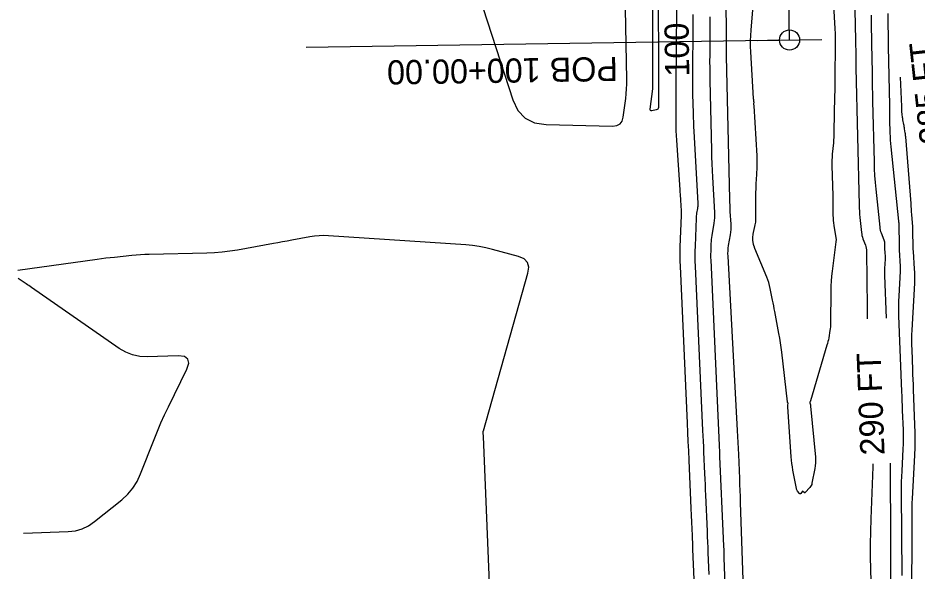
# Model space of a CAD drawing. Extents: x 1768942 to 1774819, y 723037 to 732099.
# Drawn here: x 1770638.6 to 1770861.8, y 724105.6 to 724242.8 of the extents above; entities that cross this region are included whole.
import ezdxf

# ---------------------------------------------------------------- set-up
doc = ezdxf.new("R2010")
doc.units = 0
for name, color, linetype in [('R_Contour Annot', 7, 'Continuous'), ('R_Contours', 7, 'Continuous'), ('R_Horz Alg', 7, 'Continuous'), ('R_Horz Alg Annot', 7, 'Continuous')]:
    doc.layers.add(name, color=color, linetype=linetype)

msp = doc.modelspace()

# ---------------------------------------------------------------- linework, layer by layer
at = {"layer": 'R_Contours'}
for points in [[(1770818.67, 724101), (1770817.99, 724122.58), (1770817.94, 724124.06), (1770817.88, 724125.55), (1770817.83, 724127.04), (1770817.77, 724128.52), (1770817.51, 724134.47), (1770817.45, 724135.96), (1770817.38, 724137.45), (1770817.3, 724138.93), (1770817.22, 724140.42), (1770814.87, 724183.68), (1770814.85, 724184.34), (1770814.87, 724185.01), (1770814.93, 724185.67), (1770815.02, 724186.33), (1770815.46, 724188.97), (1770815.55, 724189.63), (1770815.61, 724190.29), (1770815.63, 724190.95), (1770815.61, 724191.62), (1770815.43, 724194.81), (1770815.4, 724195.57), (1770815.36, 724196.32), (1770815.34, 724197.08), (1770815.32, 724197.83), (1770814.51, 724233.31), (1770814.5, 724233.99), (1770814.49, 724234.67), (1770814.49, 724235.35), (1770814.49, 724236.03), (1770814.51, 724238.78), (1770814.51, 724239.45), (1770814.51, 724240.11), (1770814.5, 724240.78), (1770814.48, 724241.44), (1770813.28, 724283.02)], [(1770845.74, 724278.99), (1770846.44, 724240.38), (1770846.46, 724239.55), (1770846.47, 724238.71), (1770846.49, 724237.88), (1770846.5, 724237.05), (1770846.56, 724233.71), (1770846.58, 724232.88), (1770846.59, 724232.05), (1770846.61, 724231.21), (1770846.63, 724230.38), (1770847.4, 724196.35), (1770847.43, 724195.59), (1770847.47, 724194.83), (1770847.53, 724194.07), (1770847.6, 724193.31), (1770847.99, 724189.59), (1770848.04, 724189.18), (1770848.12, 724188.78), (1770848.23, 724188.38), (1770848.37, 724187.99), (1770848.96, 724186.44), (1770849.09, 724186.05), (1770849.18, 724185.66), (1770849.24, 724185.25), (1770849.26, 724184.84), (1770849.39, 724170.97), (1770849.43, 724168.51), (1770849.44, 724168.17)], [(1770750.93, 724254.89), (1770761.48, 724222.47), (1770762.72, 724219.84), (1770764.51, 724217.95), (1770766.84, 724216.78), (1770769.71, 724216.34), (1770786.23, 724215.94), (1770787.27, 724216.06), (1770788.06, 724216.48), (1770788.59, 724217.19), (1770788.87, 724218.2), (1770789.48, 724222.83), (1770789.61, 724223.99), (1770789.7, 724225.16), (1770789.75, 724226.32), (1770789.75, 724227.49), (1770789.45, 724245.06)], [(1770797.55, 724250.14), (1770797.6, 724228.6), (1770797.6, 724228.31), (1770797.6, 724228.02), (1770797.6, 724227.72), (1770797.59, 724227.43), (1770797.58, 724226.25), (1770797.58, 724225.95), (1770797.58, 724225.66), (1770797.58, 724225.37), (1770797.58, 724225.07), (1770797.58, 724220.6), (1770797.55, 724220.35), (1770797.45, 724220.16), (1770797.28, 724220.03), (1770797.05, 724219.95), (1770795.98, 724219.75), (1770795.75, 724219.74), (1770795.6, 724219.81), (1770795.52, 724219.95), (1770795.52, 724220.18), (1770796.18, 724225.21), (1770796.21, 724225.5), (1770796.23, 724225.78), (1770796.24, 724226.07), (1770796.24, 724226.36), (1770796.22, 724227.51), (1770796.22, 724227.8), (1770796.22, 724228.09), (1770796.21, 724228.38), (1770796.21, 724228.67), (1770796.18, 724250.31)], [(1770841.07, 724245.85), (1770841.39, 724240.15), (1770841.45, 724238.87), (1770841.49, 724237.59), (1770841.5, 724236.31), (1770841.5, 724235.03), (1770841.42, 724229.08), (1770841.39, 724227.66), (1770841.37, 724226.24), (1770841.35, 724224.82), (1770841.33, 724223.4), (1770841.17, 724214.59), (1770841.15, 724213.88), (1770841.12, 724213.17), (1770841.07, 724212.47), (1770841.01, 724211.77), (1770840.74, 724208.95), (1770840.69, 724208.25), (1770840.65, 724207.54), (1770840.64, 724206.84), (1770840.65, 724206.13), (1770840.85, 724198.72), (1770840.87, 724198.1), (1770840.88, 724197.49), (1770840.89, 724196.87), (1770840.89, 724196.25), (1770840.91, 724193.77), (1770840.93, 724193.16), (1770840.97, 724192.55), (1770841.04, 724191.94), (1770841.13, 724191.33), (1770841.72, 724187.72), (1770841.73, 724187.71), (1770841.73, 724187.7), (1770841.72, 724187.69), (1770841.72, 724187.67), (1770841.71, 724187.63), (1770841.71, 724187.62), (1770841.7, 724187.61), (1770841.7, 724187.6), (1770841.7, 724187.59), (1770841.65, 724187.38), (1770841.64, 724187.34), (1770841.64, 724187.3), (1770841.63, 724187.25), (1770841.62, 724187.21), (1770840.71, 724179.97), (1770840.57, 724178.75), (1770840.47, 724177.52), (1770840.41, 724176.3), (1770840.38, 724175.07), (1770840.32, 724167.09), (1770840.31, 724166.62), (1770840.28, 724166.16), (1770840.23, 724165.7), (1770840.16, 724165.25), (1770839.85, 724163.42), (1770839.77, 724162.97), (1770839.67, 724162.51), (1770839.56, 724162.06), (1770839.43, 724161.62), (1770835.38, 724147.83), (1770835.36, 724147.79), (1770835.34, 724147.74), (1770835.32, 724147.7), (1770835.29, 724147.65), (1770835.19, 724147.48), (1770835.17, 724147.44), (1770835.16, 724147.39), (1770835.16, 724147.34), (1770835.17, 724147.3), (1770835.3, 724146.86), (1770835.32, 724146.77), (1770835.35, 724146.68), (1770835.36, 724146.59), (1770835.37, 724146.5), (1770836.56, 724133.86), (1770836.6, 724133.15), (1770836.59, 724132.43), (1770836.53, 724131.72), (1770836.42, 724131.01), (1770835.71, 724127.38), (1770835.63, 724127.08), (1770835.51, 724126.8), (1770835.36, 724126.54), (1770835.16, 724126.3), (1770834.01, 724125.04), (1770833.95, 724124.99), (1770833.89, 724124.97), (1770833.82, 724124.99), (1770833.76, 724125.04), (1770833.37, 724125.44), (1770832.91, 724124.85), (1770832.83, 724124.77), (1770832.75, 724124.75), (1770832.67, 724124.77), (1770832.59, 724124.85), (1770832.12, 724125.45), (1770832.02, 724125.59), (1770831.95, 724125.74), (1770831.89, 724125.89), (1770831.85, 724126.06), (1770830.99, 724130.64), (1770830.85, 724131.46), (1770830.73, 724132.29), (1770830.64, 724133.12), (1770830.57, 724133.95), (1770829.73, 724146.33), (1770829.72, 724146.43), (1770829.72, 724146.52), (1770829.72, 724146.61), (1770829.73, 724146.71), (1770829.77, 724147.21), (1770829.77, 724147.23), (1770829.76, 724147.26), (1770829.75, 724147.29), (1770829.74, 724147.32), (1770829.68, 724147.42), (1770829.66, 724147.44), (1770829.65, 724147.47), (1770829.64, 724147.5), (1770829.64, 724147.53), (1770828.19, 724159.91), (1770828.04, 724161.07), (1770827.88, 724162.22), (1770827.69, 724163.37), (1770827.49, 724164.51), (1770826.47, 724169.93), (1770826.34, 724170.65), (1770826.2, 724171.38), (1770826.06, 724172.1), (1770825.91, 724172.82), (1770825.33, 724175.71), (1770825.17, 724176.43), (1770824.98, 724177.14), (1770824.74, 724177.83), (1770824.48, 724178.52), (1770821.54, 724185.58), (1770821.5, 724185.67), (1770821.47, 724185.76), (1770821.43, 724185.85), (1770821.4, 724185.95), (1770821.28, 724186.32), (1770821.26, 724186.41), (1770821.23, 724186.5), (1770821.21, 724186.6), (1770821.19, 724186.69), (1770821.05, 724187.59), (1770821.02, 724187.77), (1770821.01, 724187.95), (1770821.01, 724188.14), (1770821.03, 724188.32), (1770821.11, 724189.11), (1770821.14, 724189.31), (1770821.17, 724189.5), (1770821.2, 724189.69), (1770821.25, 724189.88), (1770821.62, 724191.44), (1770821.69, 724191.76), (1770821.74, 724192.09), (1770821.77, 724192.42), (1770821.78, 724192.75), (1770821.81, 724199.57), (1770821.82, 724200.33), (1770821.84, 724201.08), (1770821.87, 724201.83), (1770821.91, 724202.59), (1770822.1, 724205.6), (1770822.13, 724206.35), (1770822.14, 724207.1), (1770822.13, 724207.85), (1770822.1, 724208.6), (1770821.32, 724220.98), (1770821.32, 724221.09), (1770821.31, 724221.2), (1770821.31, 724221.31), (1770821.31, 724221.42), (1770821.32, 724221.93), (1770821.31, 724222.01), (1770821.31, 724222.08), (1770821.3, 724222.16), (1770821.29, 724222.23), (1770821.24, 724222.53), (1770821.22, 724222.6), (1770821.21, 724222.68), (1770821.21, 724222.75), (1770821.2, 724222.83), (1770820.52, 724234.36), (1770820.46, 724235.71), (1770820.46, 724237.06), (1770820.5, 724238.41), (1770820.59, 724239.76), (1770821.17, 724246.75)], [(1770802.06, 724244.71), (1770801.9, 724226.35), (1770801.9, 724225.19), (1770801.89, 724224.03), (1770801.89, 724222.87), (1770801.89, 724221.72), (1770801.89, 724217.08), (1770801.9, 724215.93), (1770801.93, 724214.77), (1770801.98, 724213.61), (1770802.05, 724212.46), (1770802.88, 724200.14), (1770802.91, 724199.6), (1770802.95, 724199.07), (1770802.99, 724198.54), (1770803.03, 724198), (1770803.19, 724195.87), (1770803.22, 724195.34), (1770803.24, 724194.8), (1770803.24, 724194.27), (1770803.23, 724193.74), (1770802.94, 724186), (1770802.9, 724184.8), (1770802.9, 724183.61), (1770802.91, 724182.42), (1770802.95, 724181.22), (1770804.73, 724142.26), (1770804.83, 724139.97), (1770804.93, 724137.69), (1770805.04, 724135.41), (1770805.13, 724133.12), (1770805.66, 724121.09), (1770805.73, 724119.42), (1770805.8, 724117.74), (1770805.95, 724114.39), (1770805.98, 724113.55), (1770806.02, 724112.71), (1770806.05, 724111.87), (1770806.09, 724111.04), (1770806.7, 724095.99)], [(1770810.18, 724104.71), (1770809.97, 724110.11), (1770809.91, 724111.45), (1770809.85, 724112.8), (1770809.8, 724114.15), (1770809.74, 724115.5), (1770809.35, 724124.41), (1770809.3, 724125.74), (1770809.24, 724127.08), (1770809.18, 724128.42), (1770809.12, 724129.76), (1770808.89, 724135.11), (1770808.83, 724136.44), (1770808.77, 724137.78), (1770808.71, 724139.12), (1770808.65, 724140.45), (1770806.8, 724181.19), (1770806.75, 724182.45), (1770806.74, 724183.7), (1770806.74, 724184.95), (1770806.78, 724186.21), (1770807.04, 724193.13), (1770807.05, 724193.43), (1770807.08, 724193.73), (1770807.12, 724194.03), (1770807.16, 724194.33), (1770807.36, 724195.52), (1770807.4, 724195.82), (1770807.42, 724196.12), (1770807.43, 724196.42), (1770807.43, 724196.72), (1770806.45, 724214.66), (1770806.39, 724215.8), (1770806.34, 724216.95), (1770806.3, 724218.09), (1770806.27, 724219.24), (1770806.16, 724223.82), (1770806.14, 724224.97), (1770806.13, 724226.11), (1770806.13, 724227.26), (1770806.13, 724228.41), (1770806.22, 724241.16), (1770806.23, 724243.59)], [(1770854.21, 724168.35), (1770853.79, 724178.88), (1770853.78, 724179.33), (1770853.77, 724179.77), (1770853.78, 724180.21), (1770853.8, 724180.66), (1770853.92, 724182.92), (1770853.93, 724183.12), (1770853.93, 724183.32), (1770853.93, 724183.52), (1770853.92, 724183.72), (1770853.86, 724184.52), (1770853.85, 724184.72), (1770853.84, 724184.92), (1770853.83, 724185.12), (1770853.83, 724185.32), (1770853.82, 724186.59), (1770853.81, 724186.87), (1770853.77, 724187.14), (1770853.71, 724187.41), (1770853.62, 724187.67), (1770852.96, 724189.38), (1770852.83, 724189.75), (1770852.73, 724190.13), (1770852.65, 724190.52), (1770852.6, 724190.91), (1770851.62, 724200.27), (1770851.46, 724201.96), (1770851.34, 724203.66), (1770851.25, 724205.36), (1770851.19, 724207.06), (1770850.85, 724222.12), (1770850.81, 724223.9), (1770850.77, 724225.68), (1770850.74, 724227.46), (1770850.7, 724229.24), (1770850.58, 724236.37), (1770850.55, 724238.15), (1770850.52, 724239.93), (1770850.48, 724241.71), (1770850.45, 724243.49)], [(1770854.51, 724243.88), (1770854.56, 724241.15), (1770854.6, 724238.42), (1770854.65, 724235.69), (1770854.91, 724221.02), (1770854.93, 724220.17), (1770854.94, 724219.32), (1770854.96, 724218.46), (1770854.98, 724217.61), (1770855.06, 724214.19), (1770855.09, 724213.34), (1770855.13, 724212.49), (1770855.19, 724211.64), (1770855.27, 724210.79), (1770857.2, 724192.35), (1770857.2, 724192.26), (1770857.21, 724192.18), (1770857.22, 724192.09), (1770857.23, 724192.01), (1770857.27, 724191.53), (1770857.27, 724191.5), (1770857.27, 724191.45), (1770857.27, 724191.45), (1770857.27, 724191.44), (1770857.27, 724191.43), (1770857.27, 724191.42), (1770857.31, 724186.5), (1770857.31, 724185.95), (1770857.33, 724185.41), (1770857.36, 724184.86), (1770857.39, 724184.31), (1770857.54, 724182.13), (1770857.57, 724181.58), (1770857.59, 724181.04), (1770857.58, 724180.49), (1770857.56, 724179.94), (1770857.23, 724173.77), (1770857.18, 724172.56), (1770857.15, 724171.35), (1770857.16, 724170.14), (1770857.19, 724168.92), (1770857.94, 724150.16), (1770857.99, 724148.97), (1770858.03, 724147.79), (1770858.08, 724146.6), (1770858.13, 724145.41), (1770858.31, 724140.66), (1770858.34, 724139.47), (1770858.35, 724138.29), (1770858.33, 724137.1), (1770858.28, 724135.91), (1770857.98, 724130.38), (1770857.92, 724129.06), (1770857.88, 724127.74), (1770857.86, 724126.42), (1770857.86, 724125.1), (1770857.98, 724104.49)], [(1770810.36, 724243.07), (1770810.37, 724241.52), (1770810.37, 724239.97), (1770810.32, 724233.56), (1770810.31, 724231.97), (1770810.32, 724230.39), (1770810.34, 724228.81), (1770810.37, 724227.22), (1770810.76, 724210), (1770810.8, 724208.31), (1770810.86, 724206.63), (1770810.93, 724204.95), (1770811.02, 724203.27), (1770811.5, 724194.56), (1770811.51, 724193.88), (1770811.5, 724193.2), (1770811.44, 724192.53), (1770811.35, 724191.86), (1770810.84, 724188.83), (1770810.76, 724188.33), (1770810.71, 724187.83), (1770810.66, 724187.33), (1770810.63, 724186.82), (1770810.56, 724184.8), (1770810.55, 724184.3), (1770810.54, 724183.79), (1770810.55, 724183.29), (1770810.57, 724182.78), (1770812.58, 724138.65), (1770812.59, 724138.26), (1770812.61, 724137.87), (1770812.63, 724137.48), (1770812.65, 724137.09), (1770812.75, 724134.75), (1770812.78, 724133.97), (1770813.66, 724113.69), (1770813.68, 724113.29), (1770813.69, 724112.89), (1770813.71, 724112.49), (1770813.73, 724112.09), (1770813.79, 724110.49), (1770813.81, 724110.09), (1770813.82, 724109.69), (1770813.84, 724109.29), (1770813.85, 724108.89), (1770814.58, 724088.63)], [(1770860.52, 724103.21), (1770860.56, 724111.37), (1770860.57, 724112.38), (1770860.57, 724113.39), (1770860.57, 724114.41), (1770860.56, 724115.42), (1770860.54, 724119.46), (1770860.54, 724120.47), (1770860.56, 724121.48), (1770860.59, 724122.49), (1770860.63, 724123.5), (1770861.21, 724134.37), (1770861.29, 724136.24), (1770861.33, 724138.11), (1770861.32, 724139.99), (1770861.27, 724141.86), (1770860.93, 724150.65), (1770860.88, 724151.87), (1770860.83, 724153.1), (1770860.78, 724154.33), (1770860.73, 724155.56), (1770860.54, 724160.47), (1770860.5, 724161.7), (1770860.5, 724162.92), (1770860.52, 724164.15), (1770860.57, 724165.38), (1770861.2, 724176.97), (1770861.23, 724177.86), (1770861.24, 724178.75), (1770861.22, 724179.65), (1770861.17, 724180.54), (1770860.87, 724184.88), (1770860.83, 724185.39), (1770860.81, 724185.9), (1770860.8, 724186.41), (1770860.79, 724186.92), (1770860.77, 724188.95), (1770860.77, 724189.46), (1770860.75, 724189.97), (1770860.73, 724190.48), (1770860.7, 724190.99), (1770860.5, 724194.04), (1770860.45, 724194.72), (1770860.4, 724195.39), (1770860.35, 724196.07), (1770860.3, 724196.75), (1770858.97, 724213.3), (1770858.95, 724213.56), (1770858.92, 724213.81), (1770858.89, 724214.06), (1770858.85, 724214.31), (1770858.7, 724215.31), (1770858.66, 724215.56), (1770858.61, 724215.81), (1770858.57, 724216.06), (1770858.52, 724216.31), (1770858.27, 724217.54), (1770858.22, 724217.81), (1770858.18, 724218.08), (1770858.14, 724218.35), (1770858.12, 724218.63), (1770858.03, 724219.72), (1770858.01, 724219.99), (1770857.99, 724220.27), (1770857.98, 724220.54), (1770857.97, 724220.82), (1770857.72, 724228.07)], [(1770756.16, 724090.46), (1770754.16, 724138.99), (1770754.15, 724139.1), (1770754.15, 724139.22), (1770754.14, 724139.34), (1770754.13, 724139.46), (1770754.1, 724139.92), (1770754.1, 724140.04), (1770754.11, 724140.16), (1770754.12, 724140.27), (1770754.15, 724140.38), (1770765.21, 724179.5), (1770765.41, 724180.97), (1770765.09, 724182.15), (1770764.24, 724183.03), (1770762.88, 724183.62), (1770756.38, 724185.38), (1770754.75, 724185.77), (1770753.11, 724186.09), (1770751.45, 724186.33), (1770749.78, 724186.48), (1770715.67, 724188.75), (1770714.53, 724188.79), (1770713.38, 724188.76), (1770712.24, 724188.66), (1770711.1, 724188.48), (1770706.56, 724187.64), (1770705.43, 724187.43), (1770704.29, 724187.22), (1770703.16, 724187.02), (1770702.02, 724186.81), (1770693.07, 724185.22), (1770691.2, 724184.92), (1770689.32, 724184.7), (1770687.43, 724184.54), (1770685.53, 724184.46), (1770671.16, 724184.11), (1770670.08, 724184.07), (1770669.01, 724184.01), (1770667.93, 724183.93), (1770666.86, 724183.83), (1770662.56, 724183.4), (1770661.48, 724183.28), (1770660.41, 724183.16), (1770659.34, 724183.02), (1770658.27, 724182.88), (1770638.62, 724180.16)], [(1770639.96, 724115.01), (1770651.07, 724115.4), (1770652.87, 724115.6), (1770654.56, 724116.08), (1770656.16, 724116.83), (1770657.65, 724117.86), (1770664.37, 724123.27), (1770665.86, 724124.64), (1770667.14, 724126.16), (1770668.21, 724127.84), (1770669.07, 724129.68), (1770672.42, 724138.24), (1770673.25, 724140.29), (1770674.12, 724142.33), (1770675.03, 724144.35), (1770675.98, 724146.35), (1770680.5, 724155.63), (1770680.99, 724157.12), (1770680.8, 724158.18), (1770679.92, 724158.79), (1770678.35, 724158.96), (1770670.72, 724158.75), (1770668.86, 724158.84), (1770667.08, 724159.22), (1770665.38, 724159.88), (1770663.77, 724160.82), (1770641.95, 724175.95), (1770641.62, 724176.17), (1770641.29, 724176.4), (1770640.96, 724176.62), (1770640.63, 724176.84), (1770638.64, 724178.18)], [(1770850.82, 724132.2), (1770850.8, 724131.47), (1770850.32, 724118.51), (1770850.22, 724115.39), (1770850.18, 724112.28), (1770850.18, 724109.16), (1770850.23, 724106.04), (1770850.53, 724093.58)], [(1770855.4, 724092.46), (1770855.17, 724132.36)]]:
    msp.add_lwpolyline(points, dxfattribs=at)
at = {"layer": 'R_Horz Alg'}
msp.add_line((1770830.14, 724237.3), (1770821.12, 724822.68), dxfattribs=at)
msp.add_line((1770830.14, 724237.3), (1770821.12, 724822.68), dxfattribs=at)
for points in [[(1770830.14, 724237.3), (1770710.15, 724235.45)], [(1770822.14, 724237.18), (1770838.14, 724237.42)]]:
    msp.add_lwpolyline(points, dxfattribs=at)
msp.add_circle((1770830.14, 724237.3), 2.5, dxfattribs=at)

# ---------------------------------------------------------------- texts
at = {"layer": 'R_Contour Annot'}
for s, rotation, p in [('285 FT', 96.2962, (1770868.57, 724211.83)), ('290 FT', 92.2038, (1770853.74, 724134.41))]:
    msp.add_text(s, height=6, rotation=rotation, dxfattribs=at).set_placement(p)
at = {"layer": 'R_Horz Alg Annot'}
for s, rotation, p in [('100', 90.8827, (1770805.27, 724228.27)), ('POB 100+00.00', 180.8827, (1770787.49, 724233.14))]:
    msp.add_text(s, height=6, rotation=rotation, dxfattribs=at).set_placement(p)

doc.saveas('drawing.dxf')
